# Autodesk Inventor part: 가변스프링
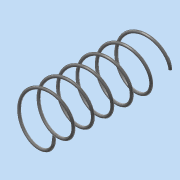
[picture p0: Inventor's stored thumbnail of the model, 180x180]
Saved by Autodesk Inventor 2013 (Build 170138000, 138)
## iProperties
Created: 2016-11
Part Number: 가변스프링
Material: 강철, 탄소
Document SubType Name: Modeling
Designer: dgall
Density: 7.87 g/cm^3
Mass: -0.0756758 g
Surface Area: 38.0291 cm^2
Volume: -0.00961573 cm^3
Author: dgall
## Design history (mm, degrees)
sketch "스케치1"
  geometry: L1 (0, 0)-(16, 0); L2 (0, 0)-(0, 84.368); L3 (0, 84.368)-(16, 84.368); C1 r 1 at (16, 0)
  constraints: 6 end point, 2 perpendicular, 1 centre point, 1 coincident, 1 horizontal, 1 vertical alignment
  dimensions: "d0" = 84.36759 distance of L1.start L2.end (derived); "d1" = 32 diameter of L3.end L2; "d2" = 2 diameter of C1
feature "코일1" sketch "스케치1" pitch "d3" = 10; turns "d5" = 6; dims "d4" = 84.36759 (= d0), "d6" = 0, angle "d7" = 90 deg, angle "d8" = 90 deg, "d9" = 0, "d10" = 0
feature "분할1"
node "작업 평면1"
feature "분할2"
node "솔리드1"
